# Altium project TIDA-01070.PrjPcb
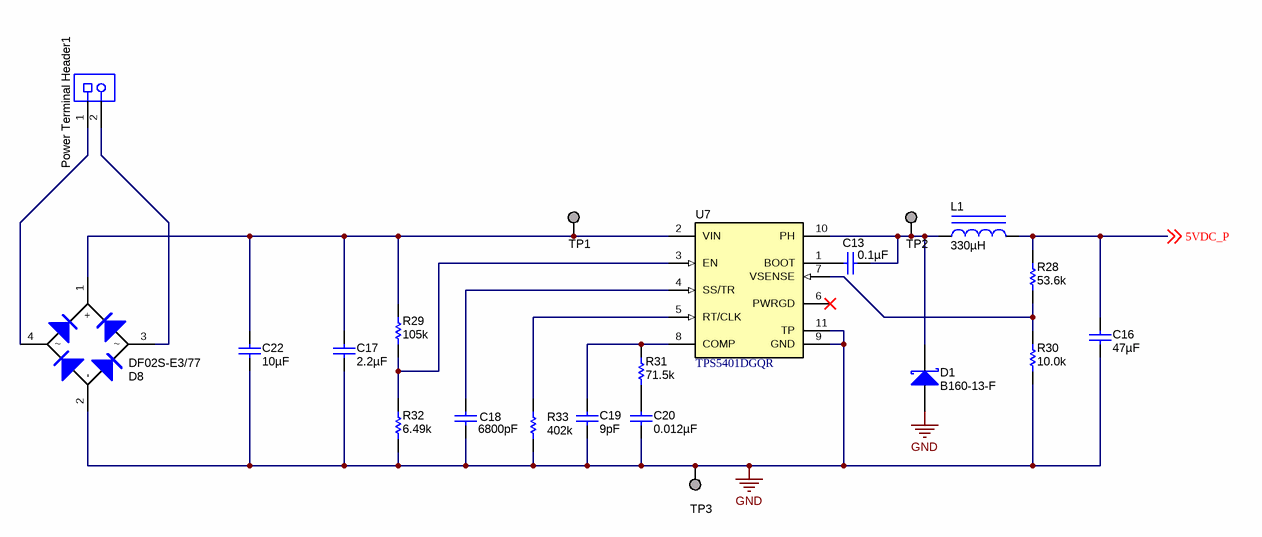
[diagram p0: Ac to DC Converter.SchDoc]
CopyrightYear: 2016; PCB_Layout: Krypton Solutions/RS; PCB_Rev: E1; PRJ_Customer: Public Release; PRJ_Engineer: Brian Dempsey; PRJ_Number: TIDA-01070; PRJ_Title: TIDA-01070; SCH_Rev: E1; TechSupport: http://www.ti.com/support; TID: TIDA-01070
5 sheets, 156 parts. Net scope: global (net labels, ports and power ports of the same name join across sheets).
Board file: TIDA-01070.PcbDoc
Sheets:
  Ac to DC Converter.SchDoc
  Board_IO_Interface.SchDoc
  Internal_Processing.SchDoc
  Sensor_Filtering.SchDoc
  TIDA-01070__EVM_Hardware.SchDoc

## Sheet Ac to DC Converter.SchDoc
size 431 x 279 mm; Date: Not shown in title block; ApprovedBy: Not shown in title block; CheckedBy: Not shown in title block; Author: Not shown in title block; CompanyName: Not shown in title block; Engineer: Not shown in title block; Organization: Not shown in title block; Address1: Not shown in title block; Address2: Not shown in title block; Address3: Not shown in title block; Address4: Not shown in title block; DocumentNumber: 1; Revision: Use project parameter SCH_Rev; SheetNumber: 1; SheetTotal: 5; PageSetup: Record=PageOptions¦CenterHorizontal=True¦CenterVertical=True¦PrintScale=1.00¦XCorrection=1.00¦YCorrection=1.00¦PrintKind=0¦BorderSize=5000000¦LeftOffset=0¦BottomOffset=0¦Orientation=2¦PaperLength=1000¦PaperWidth=1000¦Scale=100¦PaperSource=15¦PrintQuality=600¦MediaType=1¦DitherType=10¦PaperKind=Letter¦PrintScaleMode=1

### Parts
C13  ValueDisplayed: 0.1µF  [0402]  (hidden comment: GRM155R61A104KA01D)
C16  ValueDisplayed: 47µF  [1206_180]  (hidden comment: GRM31CR61A476KE15L)
C17  ValueDisplayed: 2.2µF  [1210_270]  (hidden comment: GRM32ER72A225KA35L)
C18  ValueDisplayed: 6800pF  [0805_HV]  (hidden comment: CC0805KRX7R9BB682)
C19  ValueDisplayed: 9pF  [0805_HV]  (hidden comment: GQM2195C2A9R0CB01D)
C20  ValueDisplayed: 0.012µF  [0201]  (hidden comment: GRM033C80J123KE01D)
C22  ValueDisplayed: 10µF  [2220_280]  (hidden comment: 22201C106MAT2A)
D1  B160-13-F  [SMA]
D8  DF02S-E3/77  [DF-S]
L1  ValueDisplayed: 330µH  [SDR0604]  (hidden comment: SDR0604-331KL)
Power_Terminal_Header1  (no value)  [On-Shore_OSTTE020161]
R28  ValueDisplayed: 53.6k  [0402]  (hidden comment: CRCW040253K6FKED)
R29  ValueDisplayed: 105k  [0402]  (hidden comment: CRCW0402105KFKED)
R30  ValueDisplayed: 10.0k  [0402]  (hidden comment: CRCW040210K0FKED)
R31  ValueDisplayed: 71.5k  [0402]  (hidden comment: CRCW040271K5FKED)
R32  ValueDisplayed: 6.49k  [0402]  (hidden comment: CRCW04026K49FKED)
R33  ValueDisplayed: 402k  [0402]  (hidden comment: CRCW0402402KFKED)
TP1  TESTPOINT  [Keystone_5019]  (value not drawn)  (no BOM)
TP2  TESTPOINT  [Keystone_5019]  (value not drawn)  (no BOM)
TP3  TESTPOINT  [Keystone_5019]  (value not drawn)  (no BOM)
U7  TPS5401DGQR  [DGQ0010D_N]

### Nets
GND: C16.2 C17.2 C18.2 C19.2 C20.2 C22.2 D1.2(A) D8.2(-) R30.1 R32.1 R33.1 TP3.1 U7.9(GND) U7.11(TP)
5VDC_P: C16.1 L1.2 R28.2 ; off-sheet 5VDC_P
NetC13_1: C13.1 U7.1(BOOT)
NetC13_2: C13.2 D1.1(K) L1.1 TP2.1 U7.10(PH)
NetC17_1: C17.1 C22.1 D8.1(+) R29.2 TP1.1 U7.2(VIN)
NetC18_1: C18.1 U7.4(SS/TR)
NetC19_1: C19.1 R31.2 U7.8(COMP)
NetC20_1: C20.1 R31.1
NetD8_3: D8.3 Power_Terminal_Header1.2
NetD8_4: D8.4 Power_Terminal_Header1.1
NetR28_1: R28.1 R30.2 U7.7(VSENSE)
NetR29_1: R29.1 R32.2 U7.3(EN)
NetR33_2: R33.2 U7.5(RT/CLK)

Not connected (* = marked no-connect by the designer): U7 6(PWRGD)*

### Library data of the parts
C13 = GRM155R61A104KA01D: CAP, CERM, 0.1 µF, 10 V, +/- 10%, X5R, 0402; Manufacturer: MuRata; Polarized: N; CompType: Capacitor; Value: 0.1uF; U/M: EA; Cap_F: 0.0000001; Tolerance_%: 10; Value1: Unknown; Value2: 10V; TaMin_C: -55; TaMax_C: 85; SizeArea_mm2: 0.5; SizeAreaWB_mm2: 3; SizeX_mm: 1; SizeZ_mm: 0.6; AEC Category: Q200
C16 = GRM31CR61A476KE15L: CAP, CERM, 47 µF, 10 V, +/- 10%, X5R, 1206; Manufacturer: MuRata; Polarized: N; CompType: Capacitor; Value: 47uF; U/M: EA; Cap_F: 0.000047; Tolerance_%: 10; Value1: Unknown; Value2: 10V; TaMin_C: -55; TaMax_C: 85; Cap_Case: 1206; SizeArea_mm2: 5.12; SizeAreaWB_mm2: 10.92; SizeX_mm: 3.2; SizeY_mm: 1.6; SizeZ_mm: 1.8; AEC Category: Q200
C17 = GRM32ER72A225KA35L: CAP, CERM, 2.2 µF, 100 V, +/- 10%, X7R, 1210; Manufacturer: MuRata; Polarized: N; CompType: Capacitor; Value: 2.2uF; U/M: EA; Cap_F: 0.0000022; Tolerance_%: 10; ESR_ohm: 0.007; Value1: 0.007 ohm; VDC_V: 100; Value2: 100V; IRMS_A: 4.4; TaMin_C: -55; TaMax_C: 125; Cap_Case: 1210; SizeArea_mm2: 8; SizeAreaWB_mm2: 14.7; SizeX_mm: 3.2; SizeY_mm: 2.5; SizeZ_mm: 2.7; AEC Category: Q200
C18 = CC0805KRX7R9BB682: CAP, CERM, 6800 pF, 50 V, +/- 10%, X7R, 0805; Manufacturer: Yageo America; Polarized: N; CompType: Capacitor; Value: 6800pF; U/M: EA; Cap_F: 0.0000000068; Tolerance_%: 10; Value1: Unknown; VDC_V: 50; Value2: 50V; TaMin_C: -55; TaMax_C: 125; Cap_Case: 0805; SizeArea_mm2: 2.5; SizeAreaWB_mm2: 6.75; SizeX_mm: 2; SizeY_mm: 1.25; SizeZ_mm: 1.45; AEC Category: Q200
C19 = GQM2195C2A9R0CB01D: CAP, CERM, 9 pF, 100 V, +/- 5%, C0G/NP0, 0805; Manufacturer: MuRata; Polarized: N; CompType: Capacitor; Value: 9pF; U/M: EA; Cap_F: 0.000000000009; Tolerance_%: 5; Value1: Unknown; VDC_V: 100; Value2: 100V; TaMin_C: -55; TaMax_C: 125; Cap_Case: 0805; SizeArea_mm2: 2.5; SizeAreaWB_mm2: 6.75; SizeX_mm: 2; SizeY_mm: 1.25; SizeZ_mm: 1.45; AEC Category: Q200
C20 = GRM033C80J123KE01D: CAP, CERM, 0.012 µF, 6.3 V, +/- 10%, X6S, 0201; Manufacturer: MuRata; Polarized: N; CompType: Capacitor; Value: 0.012uF; U/M: EA; Cap_F: 0.000000012; Tolerance_%: 10; Value1: Unknown; VDC_V: 6.3; Value2: 6.3V; TaMin_C: -55; TaMax_C: 105; SizeArea_mm2: 0.18; SizeAreaWB_mm2: 2.08; SizeX_mm: 0.6; SizeY_mm: 0.3; SizeZ_mm: 0.26; AEC Category: Q200
C22 = 22201C106MAT2A: CAP, CERM, 10 µF, 100 V, +/- 20%, X7R, 2220; Manufacturer: AVX; Polarized: N; CompType: Capacitor; Value: 10uF; U/M: EA; Cap_F: 0.00001; Tolerance_%: 20; Value1: Unknown; VDC_V: 100; Value2: 100V; TaMin_C: -55; TaMax_C: 125; Cap_Case: 2220; SizeAreaWB_mm2: 53.9; SizeArea_mm2: 28.5; SizeX_mm: 5.7; SizeY_mm: 5; SizeZ_mm: 2.8; AEC Category: Q200
D1 = B160-13-F: Diode, Schottky, 60 V, 1 A, SMA; Manufacturer: Diodes Inc.; U/M: EA; Vf_V: 0.7; Value: 60V; Value1: 1A; Value2: 0.7V; Io_A: 1; Vr_V: 60; TJmax_C: 150; RJC_CperW: 20; SizeAreaWB_mm2: 37.3428; SizeArea_mm2: 16.3228; SizeX_mm: 5.59; SizeY_mm: 2.92; SizeZ_mm: 2.87; AEC Category: Q101
D8 = DF02S-E3/77: Diode, Switching-Bridge, 200 V, 1 A, DF-S; Manufacturer: Vishay-Semiconductor; U/M: EA; Vf_V: 1.1; Value: 200V; Value1: 1A; Value2: 1.1V; Io_A: 1; Vr_V: 200; TJmax_C: 150; RJC_CperW: 15; SizeAreaWB_mm2: 98.794; SizeArea_mm2: 62.974; SizeX_mm: 7.4; SizeY_mm: 8.51; SizeZ_mm: 3.4; AEC Category: Q101
L1 = SDR0604-331KL: Inductor, Drum Core, Ferrite, 330 µH, 0.27 A, 2.25 ohm, SMD; Manufacturer: Bourns; Value: 330uH; Ind_H: 330.0E-6; Imax_A: 0.27; Irms: 0.27A @ 40C rise; Isat: 0.42A @ 10% inductance drop; DCR_ohm: 2.25; Value2: 0.27A; AEC Category: Q200
Power_Terminal_Header1 = OSTTE020161: Terminal Block, 2x1, 3.5mm, TH; Manufacturer: On-Shore Technology; SymbolCreator: a0412235
R28 = CRCW040253K6FKED: RES, 53.6 k, 1%, 0.063 W, 0402; Manufacturer: Vishay-Dale; CompType: Resistor; Value: 53.6k; Res_ohm: 53600; Value_Code: 53k6; Tolerance_%: 1; Power_W: 0.063; Value2: 0.063W; VDC_V: 50; TempCo: 100 ppm/C; SizeArea_mm2: 0.5; SizeZ_mm: 0.6; EIA_Code: E96; U/M: EA; AEC Category: Q200
R29 = CRCW0402105KFKED: RES, 105 k, 1%, 0.063 W, 0402; Manufacturer: Vishay-Dale; CompType: Resistor; Value: 105k; Res_ohm: 105000; Tolerance_%: 1; Power_W: 0.063; Value2: 0.063W; VDC_V: 50; TempCo: 100 ppm/C; SizeArea_mm2: 0.5; SizeZ_mm: 0.6; EIA_Code: E96; U/M: EA; AEC Category: Q200
R30 = CRCW040210K0FKED: RES, 10.0 k, 1%, 0.063 W, 0402; Manufacturer: Vishay-Dale; CompType: Resistor; Value: 10.0k; Res_ohm: 10000; Value_Code: 10k0; Tolerance_%: 1; Power_W: 0.063; Value2: 0.063W; VDC_V: 50; TempCo: 100 ppm/C; SizeArea_mm2: 0.5; SizeZ_mm: 0.6; EIA_Code: E96; U/M: EA; AEC Category: Q200
R31 = CRCW040271K5FKED: RES, 71.5 k, 1%, 0.063 W, 0402; Manufacturer: Vishay-Dale; CompType: Resistor; Value: 71.5k; Res_ohm: 71500; Value_Code: 71k5; Tolerance_%: 1; Power_W: 0.063; Value2: 0.063W; VDC_V: 50; TempCo: 100 ppm/C; SizeArea_mm2: 0.5; SizeZ_mm: 0.6; EIA_Code: E96; U/M: EA; AEC Category: Q200
R32 = CRCW04026K49FKED: RES, 6.49 k, 1%, 0.063 W, 0402; Manufacturer: Vishay-Dale; CompType: Resistor; Value: 6.49k; Res_ohm: 6490; Value_Code: 6k49; Tolerance_%: 1; Power_W: 0.063; Value2: 0.063W; VDC_V: 50; TempCo: 100 ppm/C; SizeArea_mm2: 0.5; SizeZ_mm: 0.6; EIA_Code: E96; U/M: EA; AEC Category: Q200
R33 = CRCW0402402KFKED: RES, 402 k, 1%, 0.063 W, 0402; Manufacturer: Vishay-Dale; CompType: Resistor; Value: 402k; Res_ohm: 402000; Tolerance_%: 1; Power_W: 0.063; Value2: 0.063W; VDC_V: 50; TempCo: 100 ppm/C; SizeArea_mm2: 0.5; SizeZ_mm: 0.6; EIA_Code: E96; U/M: EA; AEC Category: Q200
TP1-TP3 = 5019: Test Point, Miniature, SMT; Manufacturer: Keystone; CompType: Test Point Loop
U7 = TPS5401DGQR: Buck Step Down Regulator with 3.5 to 42 V Input and 0.8 to 39 V Output, -40 to 150 degC, 10-Pin MSOP-PowerPAD (DGQ), Green (RoHS & no Sb/Br); Manufacturer: Texas Instruments; Alternate PartNumber: Equivalent; Duty Cycle(Max)(%): 98; Iout(Max)(A): 0.5; Iq(Typ)(mA): 0.116; Rating: Catalog; Regulated Outputs(#): 1; SubFamily: Step-Down Regulator; Switch Current Limit(Typ)(A): 0.94; Vin(Max)(V): 42; Vin(Min)(V): 3.5; Vout(Max)(V): 39; Vout(Min)(V): 0.8

## Sheet Board_IO_Interface.SchDoc
size 431 x 279 mm; Date: Not shown in title block; ApprovedBy: Not shown in title block; CheckedBy: Not shown in title block; Author: Not shown in title block; CompanyName: Not shown in title block; Engineer: Brian Dempsey; Organization: Not shown in title block; Address1: Not shown in title block; Address2: Not shown in title block; Address3: Not shown in title block; Address4: Not shown in title block; DocumentNumber: 1; Revision: Use project parameter SCH_Rev; SheetNumber: 2; SheetTotal: 5; PageSetup: Record=PageOptions¦CenterHorizontal=True¦CenterVertical=True¦PrintScale=1.00¦XCorrection=1.00¦YCorrection=1.00¦PrintKind=0¦BorderSize=5000000¦LeftOffset=0¦BottomOffset=0¦Orientation=2¦PaperLength=1000¦PaperWidth=1000¦Scale=100¦PaperSource=15¦PrintQuality=600¦MediaType=1¦DitherType=10¦PaperKind=Letter¦PrintScaleMode=1
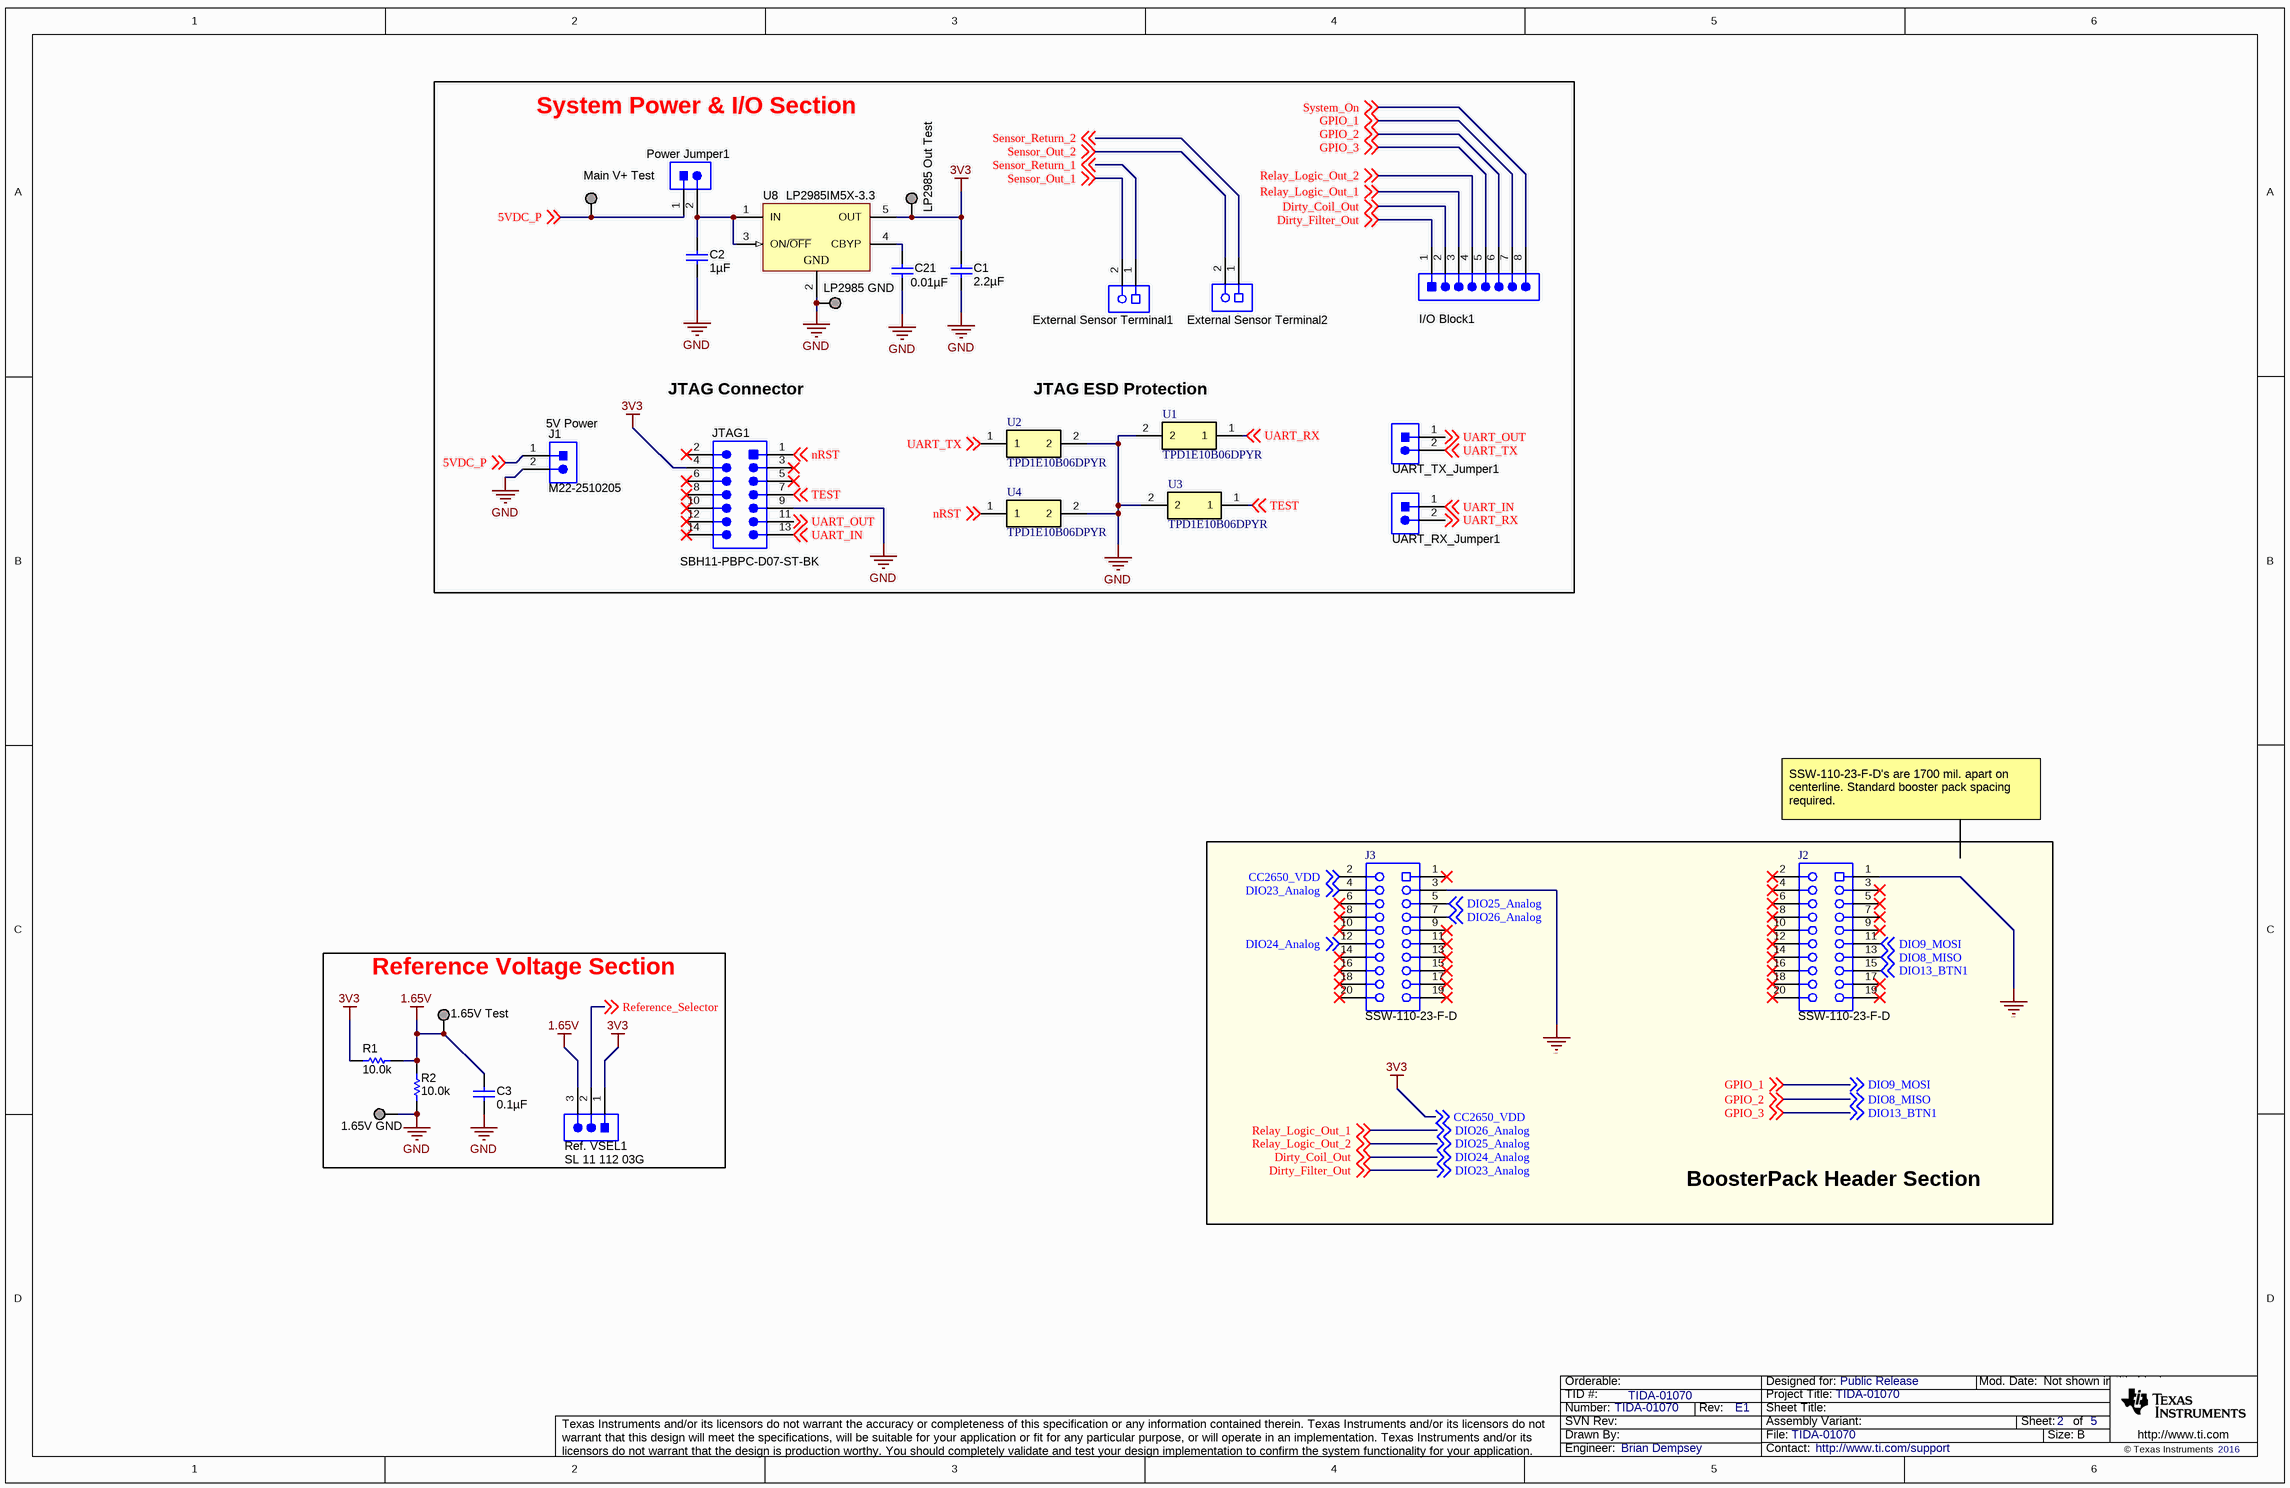
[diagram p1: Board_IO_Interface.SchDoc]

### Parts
1.65V_GND  TESTPOINT  [Keystone_5019]  (value not drawn)  (no BOM)
1.65V_Test  TESTPOINT  [Keystone_5019]  (value not drawn)  (no BOM)
C1  ValueDisplayed: 2.2µF  [0402]  (hidden comment: GRM155C80J225KE95D)
C2  ValueDisplayed: 1µF  [0402]  (hidden comment: GRM155R60J105KE19D)
C3  ValueDisplayed: 0.1µF  [0603]  (hidden comment: 0603YC104JAT2A)
C21  ValueDisplayed: 0.01µF  [0201]  (hidden comment: GRM033R60J103KA01D)
External_Sensor_Terminal1  OSTTE020161  [On-Shore_OSTTE020161]  (value not drawn)
External_Sensor_Terminal2  OSTTE020161  [On-Shore_OSTTE020161]  (value not drawn)
I/O_Block1  ED555/8DS  [On-Shore_ED555_8DS]  (value not drawn)
J1  M22-2510205  [Harwin_M22-2510205]
J2  SSW-110-23-F-D  [CONN_SSW-110-23-F-D]
J3  SSW-110-23-F-D  [CONN_SSW-110-23-F-D]
JTAG1  SBH11-PBPC-D07-ST-BK  [CONN_SBH11-PBPC-D07-ST-BK]
LP2985_GND  TESTPOINT  [Keystone_5019]  (value not drawn)  (no BOM)
LP2985_Out_Test  TESTPOINT  [Keystone_5019]  (value not drawn)  (no BOM)
Main_V+_Test  TESTPOINT  [Keystone_5019]  (value not drawn)  (no BOM)
Power_Jumper1  PartNumber  [TE_5-146278-2]  (value not drawn)
R1  ValueDisplayed: 10.0k  [0402]  (hidden comment: CRCW040210K0FKED)
R2  ValueDisplayed: 10.0k  [0402]  (hidden comment: CRCW040210K0FKED)
Ref._VSEL1  SL 11 112 03G  [Fischer_SL-11-112-03G]
U1  TPD1E10B06DPYR  [DPY0002A]
U2  TPD1E10B06DPYR  [DPY0002A]
U3  TPD1E10B06DPYR  [DPY0002A]
U4  TPD1E10B06DPYR  [DPY0002A]
U8  LP2985IM5X-3.3  [MF05A_N]
UART_RX_Jumper1  M22-2510205  [Harwin_M22-2510205]  (value not drawn)
UART_TX_Jumper1  M22-2510205  [Harwin_M22-2510205]  (value not drawn)

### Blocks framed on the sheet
System Power & I/O Section: C1 C2 C21 External_Sensor_Terminal1 External_Sensor_Terminal2 I/O_Block1 J1 JTAG1 LP2985_GND LP2985_Out_Test Main_V+_Test Power_Jumper1 U1-U4 U8 UART_RX_Jumper1 UART_TX_Jumper1
BoosterPack Header Section: J2 J3
Reference Voltage Section: 1.65V_GND 1.65V_Test C3 R1 R2 Ref._VSEL1

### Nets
1.65V: 1.65V_Test.1 C3.2 R1.1 R2.1 Ref._VSEL1.3
3V3: C1.1 J3.2 JTAG1.4 LP2985_Out_Test.1 R1.2 Ref._VSEL1.1 U8.5(OUT) ; off-sheet CC2650_VDD  [also labelled CC2650_VDD]
GND: 1.65V_GND.1 C1.2 C2.2 C3.1 C21.2 J1.2 J2.1 J3.3 JTAG1.9 LP2985_GND.1 R2.2 U1.2 U2.2 U3.2 U4.2 U8.2(GND)
5VDC_P: J1.1 Main_V+_Test.1 Power_Jumper1.1 ; off-sheet 5VDC_P
DIO8_MISO: I/O_Block1.6 J2.13 ; off-sheet DIO8_MISO, off-sheet GPIO_2  [also labelled GPIO_2]
DIO9_MOSI: I/O_Block1.7 J2.11 ; off-sheet DIO9_MOSI, off-sheet GPIO_1  [also labelled GPIO_1]
DIO13_BTN1: I/O_Block1.5 J2.15 ; off-sheet DIO13_BTN1, off-sheet GPIO_3  [also labelled GPIO_3]
DIO23_Analog: I/O_Block1.1 J3.4 ; off-sheet DIO23_Analog, off-sheet Dirty_Filter_Out  [also labelled Dirty_Filter_Out]
DIO24_Analog: I/O_Block1.2 J3.12 ; off-sheet DIO24_Analog, off-sheet Dirty_Coil_Out  [also labelled Dirty_Coil_Out]
DIO25_Analog: I/O_Block1.4 J3.5 ; off-sheet Relay_Logic_Out_2, off-sheet DIO25_Analog  [also labelled Relay_Logic_Out_2]
DIO26_Analog: I/O_Block1.3 J3.7 ; off-sheet Relay_Logic_Out_1, off-sheet DIO26_Analog  [also labelled Relay_Logic_Out_1]
nRST: JTAG1.1 U4.1 ; off-sheet nRST
Reference_Selector: Ref._VSEL1.2 ; off-sheet Reference_Selector
Sensor_Out_1: External_Sensor_Terminal1.2 ; off-sheet Sensor_Out_1
Sensor_Out_2: External_Sensor_Terminal2.2 ; off-sheet Sensor_Out_2
Sensor_Return_1: External_Sensor_Terminal1.1 ; off-sheet Sensor_Return_1
Sensor_Return_2: External_Sensor_Terminal2.1 ; off-sheet Sensor_Return_2
System_On: I/O_Block1.8 ; off-sheet System_On
TEST: JTAG1.7 U3.1 ; off-sheet TEST
UART_IN: JTAG1.13 UART_RX_Jumper1.1 ; off-sheet UART_IN
UART_OUT: JTAG1.11 UART_TX_Jumper1.1 ; off-sheet UART_OUT
UART_RX: U1.1 UART_RX_Jumper1.2 ; off-sheet UART_RX
UART_TX: U2.1 UART_TX_Jumper1.2 ; off-sheet UART_TX
NetC2_1: C2.1 Power_Jumper1.2 U8.1(IN) U8.3(ON/~{OFF})
NetC21_1: C21.1 U8.4(CBYP)

Not connected (* = marked no-connect by the designer): J2 2* 3* 4* 5* 6* 7* 8* 9* 10* 12* 14* 16* 17* 18* 19* 20*; J3 1* 6* 8* 9* 10* 11* 13* 14* 15* 16* 17* 18* 19* 20*; JTAG1 2* 3* 5* 6* 8* 10* 12* 14*

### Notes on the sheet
- (near J1) 5V Power
- JTAG Connector
- JTAG ESD Protection
- SSW-110-23-F-D's are 1700 mil. apart on centerline. Standard booster pack spacing required.

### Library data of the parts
1.65V_GND 1.65V_Test LP2985_GND LP2985_Out_Test Main_V+_Test = 5019: as TP1 on sheet Ac to DC Converter
C1 = GRM155C80J225KE95D: CAP, CERM, 2.2 µF, 6.3 V, +/- 10%, X6S, 0402; Manufacturer: MuRata; Polarized: N; CompType: Capacitor; Value: 2.2uF; U/M: EA; Cap_F: 0.0000022; Tolerance_%: 10; Value1: Unknown; VDC_V: 6.3; Value2: 6.3V; TaMin_C: -55; TaMax_C: 105; AEC Category: Q200; SizeArea_mm2: 0.5; SizeAreaWB_mm2: 3; SizeX_mm: 1; SizeZ_mm: 0.6
C2 = GRM155R60J105KE19D: CAP, CERM, 1 µF, 6.3 V, +/- 10%, X5R, 0402; Manufacturer: MuRata; Polarized: N; CompType: Capacitor; Value: 1uF; U/M: EA; Cap_F: 0.000001; Tolerance_%: 10; Value1: Unknown; VDC_V: 6.3; Value2: 6.3V; TaMin_C: -55; TaMax_C: 85; AEC Category: Q200; SizeArea_mm2: 0.5; SizeAreaWB_mm2: 3; SizeX_mm: 1; SizeZ_mm: 0.6
C3 = 0603YC104JAT2A: CAP, CERM, 0.1 µF, 16 V, +/- 5%, X7R, 0603; Manufacturer: AVX; Polarized: N; CompType: Capacitor; Value: 0.1uF; U/M: EA; Cap_F: 0.0000001; Tolerance_%: 5; ESR_ohm: 0.039; Value1: 0.039 ohm; VDC_V: 16; Value2: 16V; TaMin_C: -55; TaMax_C: 125; SizeArea_mm2: 1.28; SizeAreaWB_mm2: 4.68; SizeX_mm: 1.6; SizeY_mm: 0.8; SizeZ_mm: 1; AEC Category: Q200
C21 = GRM033R60J103KA01D: CAP, CERM, 0.01 µF, 6.3 V, +/- 10%, X5R, 0201; Manufacturer: MuRata; Polarized: N; CompType: Capacitor; Value: 0.01uF; U/M: EA; Cap_F: 0.00000001; Tolerance_%: 10; Value1: Unknown; VDC_V: 6.3; Value2: 6.3V; TaMin_C: -55; TaMax_C: 85; SizeArea_mm2: 0.18; SizeAreaWB_mm2: 2.08; SizeX_mm: 0.6; SizeY_mm: 0.3; SizeZ_mm: 0.26; AEC Category: Q200
External_Sensor_Terminal1 External_Sensor_Terminal2 = OSTTE020161: as Power_Terminal_Header1 on sheet Ac to DC Converter
I/O_Block1 = ED555/8DS: Terminal Block, 3.5mm, 8-Pos, TH; Manufacturer: On-Shore Technology; SymbolCreator: a0411947; Pitch_mm: 3.5; Gender: Male; Shrouded: Y; Row_Count: 1; ContactFinish: Brass
J1 UART_RX_Jumper1 UART_TX_Jumper1 = M22-2510205: Header, 2mm, 2x1, Gold, Black, TH; Manufacturer: Harwin; SymbolCreator: a0412235; Pitch_mm: 2; Gender: Male; Shrouded: N; Row_Count: 1; Voltage_V: 500; Cert_UL: Y
J2 J3 = SSW-110-23-F-D: Connector, Receptacle, 100mil, 10x2, Gold plated, TH; Manufacturer: Samtec; SymbolCreator: a0412235
JTAG1 = SBH11-PBPC-D07-ST-BK: Header (shrouded), 100 mil, 7x2, Gold, TH; Manufacturer: Sullins Connector Solutions; SymbolCreator: a0412235
Power_Jumper1 = 5-146278-2: Header, 100mil, 2x1, Tin, TH; Manufacturer: TE Connectivity; SymbolCreator: a0412235
R1 R2 = CRCW040210K0FKED: as R30 on sheet Ac to DC Converter
Ref._VSEL1 = SL 11 112 03G: Header, 2.54mm, 3x1, Gold, TH; Manufacturer: Fischer Elektronik; SymbolCreator: a0799628
U1-U4 = TPD1E10B06DPYR: ESD in 0402 Package with 10 pF Capacitance and 6 V Breakdown, 1 Channel, -40 to +125 degC, 2-pin X2SON (DPY), Green (RoHS & no Sb/Br); Manufacturer: Texas Instruments; Alternate PartNumber: Equivalent; Breakdown Voltage(Min)(V): 6; Eco-Plan: TBD; IEC 61000-4-2 Air-Gap(+/- kV): 30; IO Capacitance(Typ)(pF): 10; SubFamily: ESD Solution
U8 = LP2985IM5X-3.3: Micropower 150 mA Low-Noise Ultra Low-Dropout Regulator, 5-pin SOT-23; PartNumber: LP2985IM5X-3.3/NOPB; Manufacturer: Texas Instruments; PackageTopMarking: L0RB*XTT; PowerWise: N; CompType: LDO IC

## Sheet Internal_Processing.SchDoc
size 431 x 279 mm; Date: Not shown in title block; ApprovedBy: Not shown in title block; CheckedBy: Not shown in title block; Author: Not shown in title block; CompanyName: Not shown in title block; Engineer: Not shown in title block; Organization: Not shown in title block; Address1: Not shown in title block; Address2: Not shown in title block; Address3: Not shown in title block; Address4: Not shown in title block; DocumentNumber: 1; Revision: Use project parameter SCH_Rev; SheetNumber: 3; SheetTotal: 5; PageSetup: Record=PageOptions¦CenterHorizontal=True¦CenterVertical=True¦PrintScale=1.00¦XCorrection=1.00¦YCorrection=1.00¦PrintKind=0¦BorderSize=5000000¦LeftOffset=0¦BottomOffset=0¦Orientation=2¦PaperLength=1000¦PaperWidth=1000¦Scale=100¦PaperSource=15¦PrintQuality=600¦MediaType=1¦DitherType=10¦PaperKind=Letter¦PrintScaleMode=1
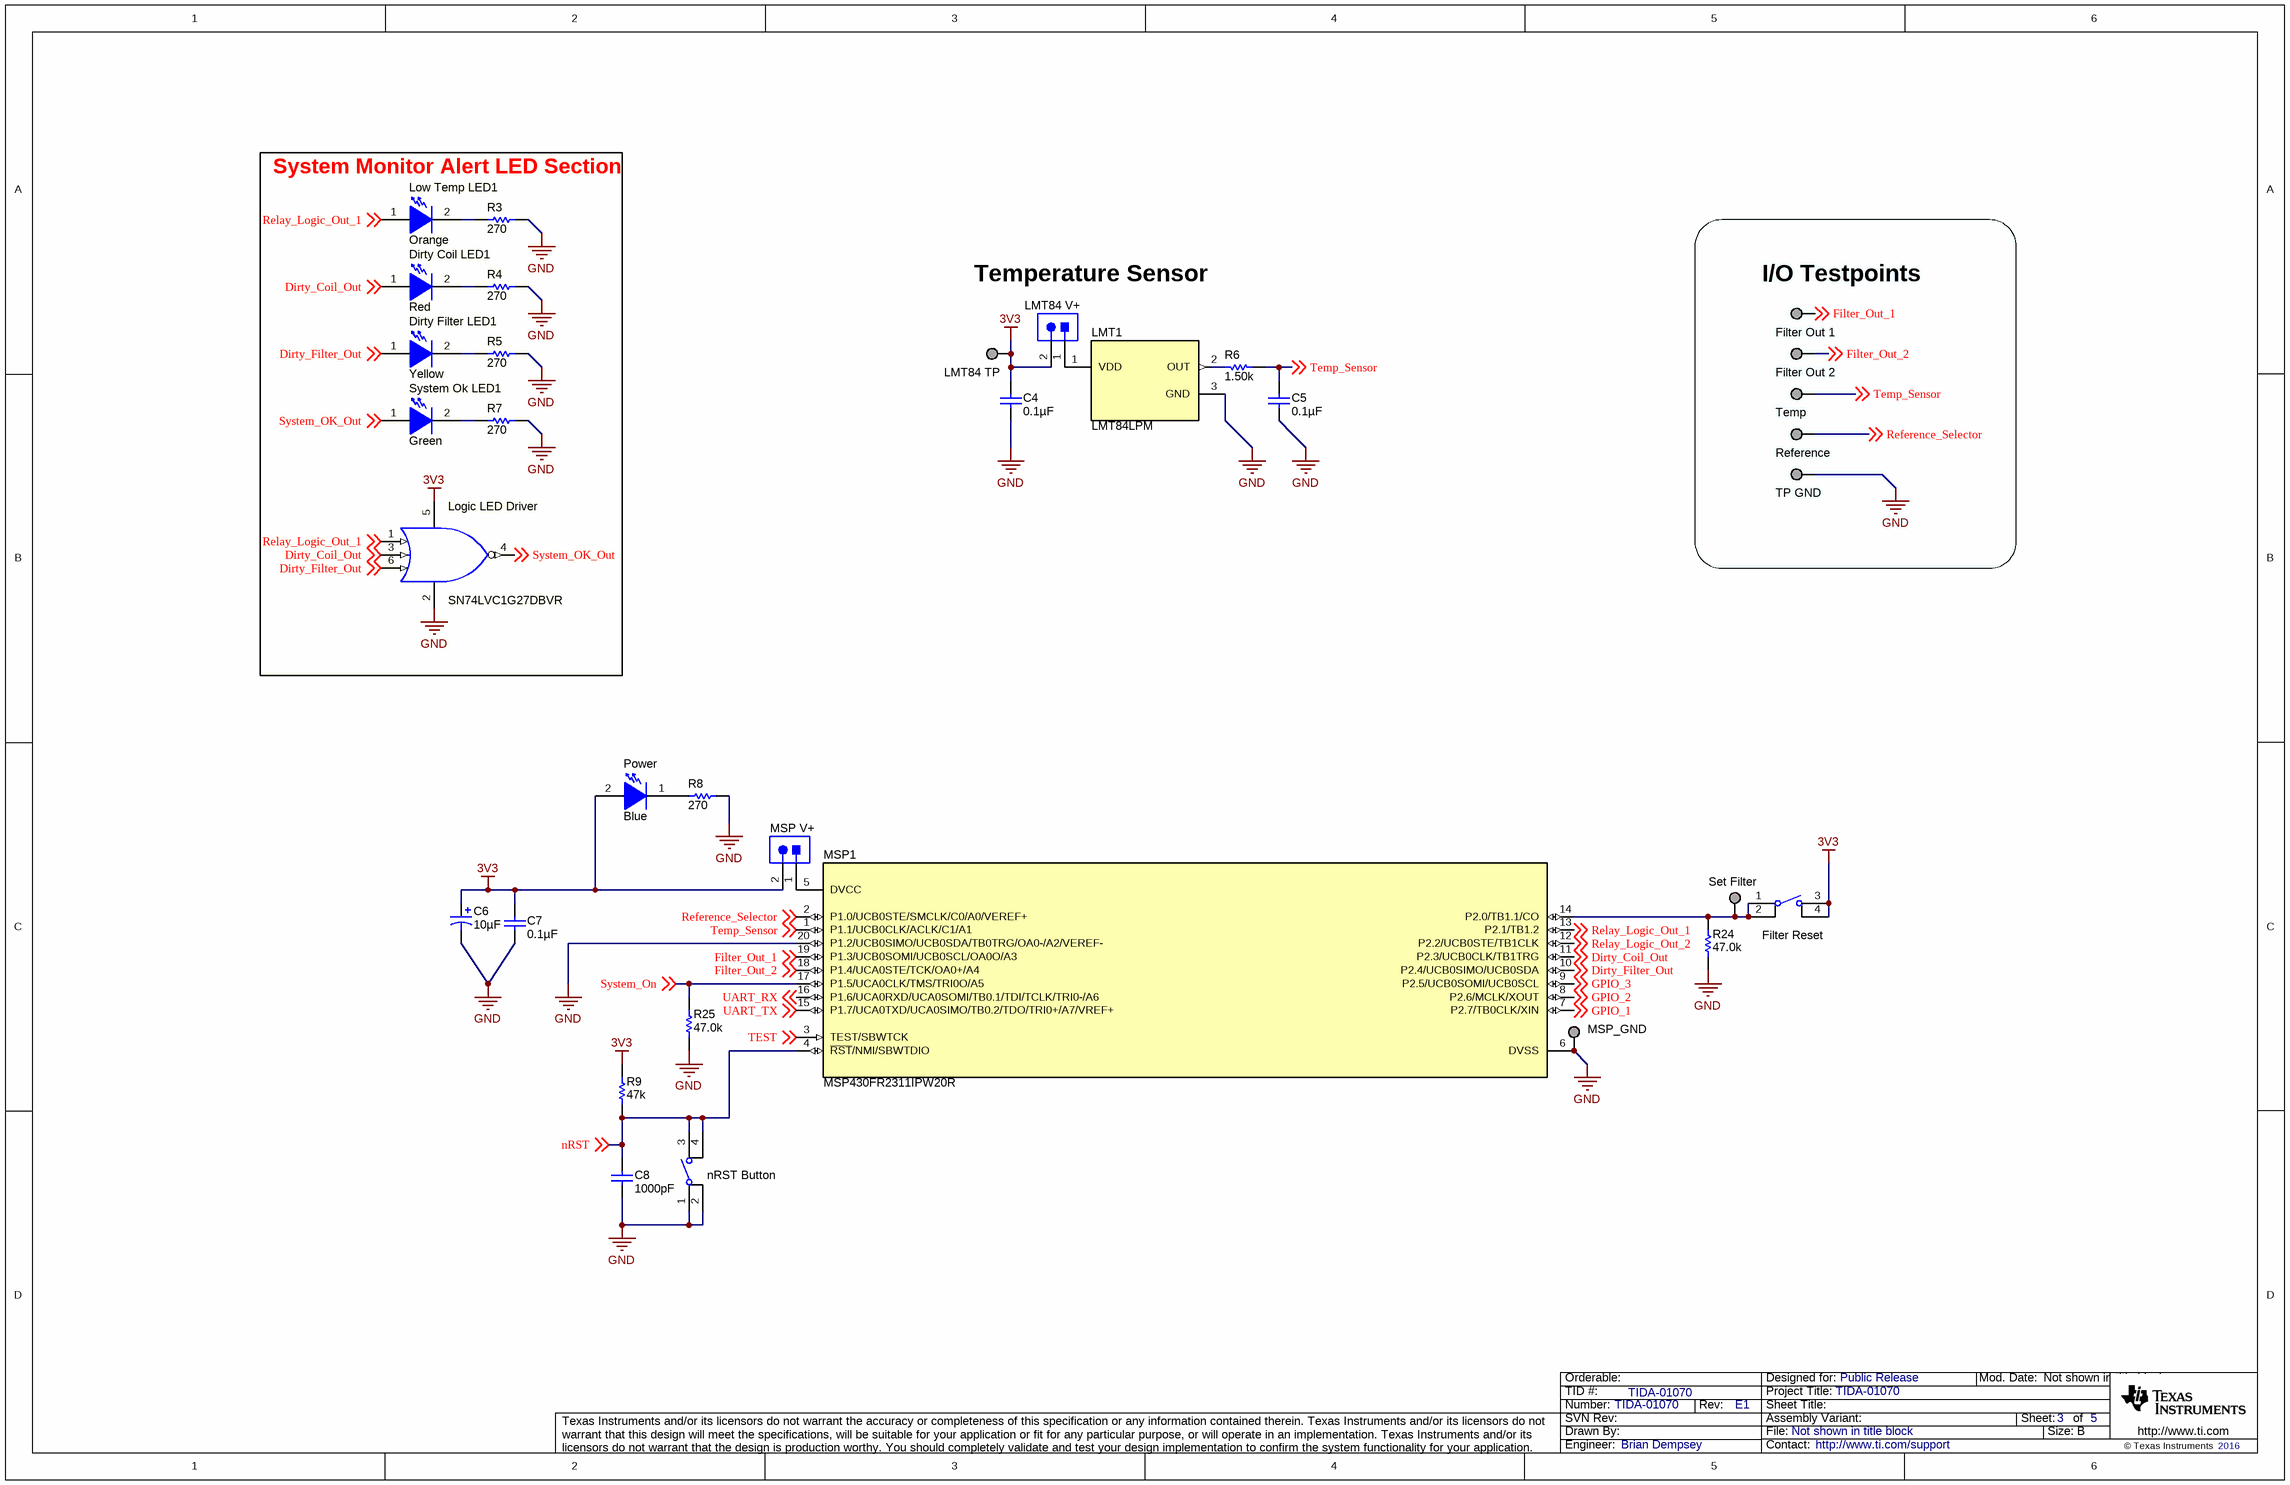
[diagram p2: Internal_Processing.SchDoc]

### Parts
C4  ValueDisplayed: 0.1µF  [0603]  (hidden comment: 0603YC104JAT2A)
C5  ValueDisplayed: 0.1µF  [0603]  (hidden comment: 0603YC104JAT2A)
C6  ValueDisplayed: 10µF  [SM_RADIAL_B]  (hidden comment: EEE-FK1E100R)
C7  ValueDisplayed: 0.1µF  [0603]  (hidden comment: 0603YC104JAT2A)
C8  ValueDisplayed: 1000pF  [0402]  (hidden comment: GRM155R71C102KA01D)
Dirty_Coil_LED1  value Red  [LED_LTST-C170_Red]  (hidden comment: LTST-C170KRKT)
Dirty_Filter_LED1  value Yellow  [LED_LTST-C170]  (hidden comment: LTST-C170KSKT)
Filter_Out_1  TESTPOINT  [Keystone_5019]  (value not drawn)  (no BOM)
Filter_Out_2  TESTPOINT  [Keystone_5019]  (value not drawn)  (no BOM)
Filter_Reset  4-1437565-1  [SW_FSM4JSMA]  (value not drawn)
LMT1  LMT84LPM  [LP0003A_straight]
LMT84_TP  TESTPOINT  [Keystone_5019]  (value not drawn)  (no BOM)
LMT84_V+  M22-2510205  [Harwin_M22-2510205]  (value not drawn)
Logic_LED_Driver  SN74LVC1G27DBVR  [DBV0006A_N]
Low_Temp_LED1  value Orange  [LTST-C170KFKT_Orange]  (hidden comment: LTST-C170KFKT)
MSP1  MSP430FR2311IPW20R  [PW0020A_N]
MSP_GND  TESTPOINT  [Keystone_5019]  (value not drawn)  (no BOM)
MSP_V+  M22-2510205  [Harwin_M22-2510205]  (value not drawn)
nRST_Button  4-1437565-1  [SW_FSM4JSMA]  (value not drawn)
Power  value Blue  [WL-SMCW_Blue]  (hidden comment: 150060BS75000)
R3  ValueDisplayed: 270  [0402]  (hidden comment: CRCW0402270RJNED)
R4  ValueDisplayed: 270  [0402]  (hidden comment: CRCW0402270RJNED)
R5  ValueDisplayed: 270  [0402]  (hidden comment: CRCW0402270RJNED)
R6  ValueDisplayed: 1.50k  [0402]  (hidden comment: CRCW04021K50FKED)
R7  ValueDisplayed: 270  [0402]  (hidden comment: CRCW0402270RJNED)
R8  ValueDisplayed: 270  [0402]  (hidden comment: CRCW0402270RJNED)
R9  ValueDisplayed: 47k  [0402]  (hidden comment: CRCW040247K0JNED)
R24  ValueDisplayed: 47.0k  [0805_HV]  (hidden comment: RG2012P-473-B-T5)
R25  ValueDisplayed: 47.0k  [0805_HV]  (hidden comment: RG2012P-473-B-T5)
Reference  TESTPOINT  [Keystone_5019]  (value not drawn)  (no BOM)
Set_Filter  TESTPOINT  [Keystone_5019]  (value not drawn)  (no BOM)
System_Ok_LED1  value Green  [LTST-C170KGKT_Green]  (hidden comment: LTST-C170KGKT)
Temp  TESTPOINT  [Keystone_5019]  (value not drawn)  (no BOM)
TP_GND  TESTPOINT  [Keystone_5019]  (value not drawn)  (no BOM)

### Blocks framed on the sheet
System Monitor Alert LED Section: Dirty_Coil_LED1 Dirty_Filter_LED1 Logic_LED_Driver Low_Temp_LED1 R3-R5 R7 System_Ok_LED1
I/O Testpoints: Filter_Out_1 Filter_Out_2 Reference Temp TP_GND

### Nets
3V3: C4.2 C6.1(+) C7.2 Filter_Reset.3 Filter_Reset.4 LMT84_TP.1 LMT84_V+.2 Logic_LED_Driver.5(VCC) MSP_V+.2 Power.2(A) R9.2
GND: C4.1 C5.1 C6.2(-) C7.1 C8.1 LMT1.3(GND) Logic_LED_Driver.2(GND) MSP1.6(DVSS) MSP1.20(P1.2/UCB0SIMO/UCB0SDA/TB0TRG/OA0-/A2/VEREF-) MSP_GND.1 nRST_Button.1 nRST_Button.2 R3.2 R4.2 R5.2 R7.2 R8.2 R24.1 R25.1 TP_GND.1
Dirty_Coil_Out: Dirty_Coil_LED1.1(A) Logic_LED_Driver.3(B) MSP1.11(P2.3/UCB0CLK/TB1TRG) ; off-sheet Dirty_Coil_Out  [project net DIO24_Analog]
Dirty_Filter_Out: Dirty_Filter_LED1.1(A) Logic_LED_Driver.6(C) MSP1.10(P2.4/UCB0SIMO/UCB0SDA) ; off-sheet Dirty_Filter_Out  [project net DIO23_Analog]
Filter_Out_1: Filter_Out_1.1 MSP1.19(P1.3/UCB0SOMI/UCB0SCL/OA0O/A3) ; off-sheet Filter_Out_1
Filter_Out_2: Filter_Out_2.1 MSP1.18(P1.4/UCA0STE/TCK/OA0+/A4) ; off-sheet Filter_Out_2
GPIO_1: MSP1.7(P2.7/TB0CLK/XIN) ; off-sheet GPIO_1  [project net DIO9_MOSI]
GPIO_2: MSP1.8(P2.6/MCLK/XOUT) ; off-sheet GPIO_2  [project net DIO8_MISO]
GPIO_3: MSP1.9(P2.5/UCB0SOMI/UCB0SCL) ; off-sheet GPIO_3  [project net DIO13_BTN1]
nRST: C8.2 MSP1.4(~{RST}/NMI/SBWTDIO) nRST_Button.3 nRST_Button.4 R9.1 ; off-sheet nRST
Reference_Selector: MSP1.2(P1.0/UCB0STE/SMCLK/C0/A0/VEREF+) Reference.1 ; off-sheet Reference_Selector
Relay_Logic_Out_1: Logic_LED_Driver.1(A) Low_Temp_LED1.1(A) MSP1.13(P2.1/TB1.2) ; off-sheet Relay_Logic_Out_1  [project net DIO26_Analog]
Relay_Logic_Out_2: MSP1.12(P2.2/UCB0STE/TB1CLK) ; off-sheet Relay_Logic_Out_2  [project net DIO25_Analog]
System_OK_Out: Logic_LED_Driver.4(Y) System_Ok_LED1.1(A) ; off-sheet System_OK_Out
System_On: MSP1.17(P1.5/UCA0CLK/TMS/TRI0O/A5) R25.2 ; off-sheet System_On
Temp_Sensor: C5.2 MSP1.1(P1.1/UCB0CLK/ACLK/C1/A1) R6.2 Temp.1 ; off-sheet Temp_Sensor
TEST: MSP1.3(TEST/SBWTCK) ; off-sheet TEST
UART_RX: MSP1.16(P1.6/UCA0RXD/UCA0SOMI/TB0.1/TDI/TCLK/TRI0-/A6) ; off-sheet UART_RX
UART_TX: MSP1.15(P1.7/UCA0TXD/UCA0SIMO/TB0.2/TDO/TRI0+/A7/VREF+) ; off-sheet UART_TX
NetDirty_Coil_LED1_2: Dirty_Coil_LED1.2(K) R4.1
NetDirty_Filter_LED1_2: Dirty_Filter_LED1.2(K) R5.1
NetFilter_Reset_1: Filter_Reset.1 Filter_Reset.2 MSP1.14(P2.0/TB1.1/CO) R24.2 Set_Filter.1
NetLMT1_1: LMT1.1(VDD) LMT84_V+.1
NetLMT1_2: LMT1.2(OUT) R6.1
NetLow_Temp_LED1_2: Low_Temp_LED1.2(K) R3.1
NetMSP1_5: MSP1.5(DVCC) MSP_V+.1
NetPower_1: Power.1(K) R8.1
NetR7_1: R7.1 System_Ok_LED1.2(K)

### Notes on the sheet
- Temperature Sensor

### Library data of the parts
C4 C5 C7 = 0603YC104JAT2A: as C3 on sheet Board_IO_Interface
C6 = EEE-FK1E100R: CAP, AL, 10 µF, 25 V, +/- 20%, 1.35 ohm, AEC-Q200 Grade 2, SMD; Manufacturer: Panasonic; Polarized: Y; CompType: Capacitor; Value: 10uF; U/M: EA; Cap_F: 0.00001; Tolerance_%: 20; VDC_V: 25; Value2: 25V; ESR_ohm: 1.35; IRMS_A: 0.09; TaMin_C: -55; TaMax_C: 105; Cap_Case: B; AEC Category: Q200; AEC Grade: 2
C8 = GRM155R71C102KA01D: CAP, CERM, 1000 pF, 16 V, +/- 10%, X7R, 0402; Manufacturer: MuRata; Polarized: N; CompType: Capacitor; Value: 1000pF; U/M: EA; Cap_F: 0.000000001; Tolerance_%: 10; Value1: Unknown; VDC_V: 16; Value2: 16V; TaMin_C: -55; TaMax_C: 125; SizeArea_mm2: 0.5; SizeAreaWB_mm2: 3; SizeX_mm: 1; SizeZ_mm: 0.6; AEC Category: Q200
Dirty_Coil_LED1 = LTST-C170KRKT: LED, Red, SMD; Manufacturer: Lite-On; Vf_V: 2; Value2: 2V; Io_A: 0.02; Value1: W; SizeAreaWB_mm2: 6.75; SizeArea_mm2: 2.5; SizeY_mm: 1.25; SizeZ_mm: 1.2; U/M: EA
Dirty_Filter_LED1 = LTST-C170KSKT: LED, Yellow , SMD; Manufacturer: Lite-On; Vf_V: 2; Value2: 2V; Io_A: 0.02; Value1: W; SizeAreaWB_mm2: 6.75; SizeArea_mm2: 2.5; SizeY_mm: 1.25; SizeZ_mm: 1.2; U/M: EA
Filter_Out_1 Filter_Out_2 LMT84_TP MSP_GND Reference Set_Filter Temp TP_GND = 5019: as TP1 on sheet Ac to DC Converter
Filter_Reset nRST_Button = 4-1437565-1: Switch, Tactile, SPST-NO, 0.05A, 12V, SMT; Manufacturer: TE Connectivity; SymbolCreator: a0412235; VDC_V: 12; SwitchFunction: Off-Mom; PositionCount: 1; CurrentRating_mA: 50
LMT1 = LMT84LPM: 1.5V, TO-92, Analog Temperature Sensor with Class-AB Output, LP0003A; Manufacturer: Texas Instruments; SymbolCreator: a0411947; SizeArea_mm2: 18.4; SizeAreaWB_mm2: 39.76; SizeX_mm: 3.68; SizeY_mm: 5; SizeZ_mm: 9.33; CompType: IC; U/M: EA
LMT84_V+ MSP_V+ = M22-2510205: as J1 on sheet Board_IO_Interface
Logic_LED_Driver = SN74LVC1G27DBVR: Single 3-Input Positive-NOR Gate, DBV0006A; Manufacturer: Texas Instruments; SymbolCreator: Altium; SizeArea_mm2: 8.12; SizeAreaWB_mm2: 14.82; SizeX_mm: 2.8; SizeY_mm: 2.9; SizeZ_mm: 1.45; CompType: IC; U/M: EA
Low_Temp_LED1 = LTST-C170KFKT: LED, Orange, SMD; Manufacturer: Lite-On; Vf_V: 2; Value2: 2V; Io_A: 0.02; Value1: W; U/M: EA
MSP1 = MSP430FR2311IPW20R: Mixed-Signal Microcontroller, PW0020A; Manufacturer: Texas Instruments; SymbolCreator: Altium; SizeArea_mm2: 43.56; SizeAreaWB_mm2: 73.96; SizeX_mm: 6.6; SizeZ_mm: 1.2; CompType: IC; U/M: EA
Power = 150060BS75000: LED, Blue, SMD; Manufacturer: Wurth Elektronik; Vf_V: 3.2; Value2: 3.2V; Io_A: 0.03; Vr_V: 5; Tjmax_C: 85; Power_TotalModule: 0.105; Value1: 0.105W; Angle: 140; U/M: EA
R3-R5 R7 R8 = CRCW0402270RJNED: RES, 270, 5%, 0.063 W, 0402; Manufacturer: Vishay-Dale; CompType: Resistor; Value: 270; Value_Code: 270R; Tolerance_%: 5; Power_W: 0.063; Value2: 0.063W; VDC_V: 50; TempCo: 200 ppm/C; SizeArea_mm2: 0.5; SizeX_mm: 1; SizeZ_mm: 0.6; EIA_Code: E24; U/M: EA; AEC Category: Q200
R6 = CRCW04021K50FKED: RES, 1.50 k, 1%, 0.063 W, 0402; Manufacturer: Vishay-Dale; CompType: Resistor; Value: 1.50k; Res_ohm: 1500; Value_Code: 1k50; Tolerance_%: 1; Power_W: 0.063; Value2: 0.063W; VDC_V: 50; TempCo: 100 ppm/C; SizeArea_mm2: 0.5; SizeZ_mm: 0.6; EIA_Code: E96; U/M: EA; AEC Category: Q200
R9 = CRCW040247K0JNED: RES, 47 k, 5%, 0.063 W, 0402; Manufacturer: Vishay-Dale; CompType: Resistor; Value: 47k; Res_ohm: 47000; Value_Code: 47k0; Tolerance_%: 5; Power_W: 0.063; Value2: 0.063W; VDC_V: 50; TempCo: 200 ppm/C; SizeArea_mm2: 0.5; SizeX_mm: 1; SizeZ_mm: 0.6; EIA_Code: E24; U/M: EA; AEC Category: Q200
R24 R25 = RG2012P-473-B-T5: RES, 47.0 k, 0.1%, 0.125 W, 0805; Manufacturer: Susumu Co Ltd; CompType: Resistor; Value: 47.0k; Res_ohm: 47000; Value_Code: 47k0; Tolerance_%: 0.1; Power_W: 0.125; Value2: 0.125W; VDC_V: 100; TempCo: 25 ppm/C; SizeArea_mm2: 2.5; SizeX_mm: 2; SizeY_mm: 1.25; SizeZ_mm: 1.45; EIA_Code: E192; U/M: EA; AEC Category: Q200
System_Ok_LED1 = LTST-C170KGKT: LED, Green, SMD; Manufacturer: Lite-On; Vf_V: 2; Value2: 2V; Io_A: 0.02; Value1: W; U/M: EA

## Sheet Sensor_Filtering.SchDoc
size 431 x 279 mm; Date: Not shown in title block; ApprovedBy: Not shown in title block; CheckedBy: Not shown in title block; Author: Not shown in title block; CompanyName: Not shown in title block; Engineer: Not shown in title block; Organization: Not shown in title block; Address1: Not shown in title block; Address2: Not shown in title block; Address3: Not shown in title block; Address4: Not shown in title block; DocumentNumber: 1; Revision: Use project parameter SCH_Rev; SheetNumber: 4; SheetTotal: 5; PageSetup: Record=PageOptions¦CenterHorizontal=True¦CenterVertical=True¦PrintScale=1.00¦XCorrection=1.00¦YCorrection=1.00¦PrintKind=0¦BorderSize=5000000¦LeftOffset=0¦BottomOffset=0¦Orientation=2¦PaperLength=1000¦PaperWidth=1000¦Scale=100¦PaperSource=15¦PrintQuality=600¦MediaType=1¦DitherType=10¦PaperKind=Letter¦PrintScaleMode=1
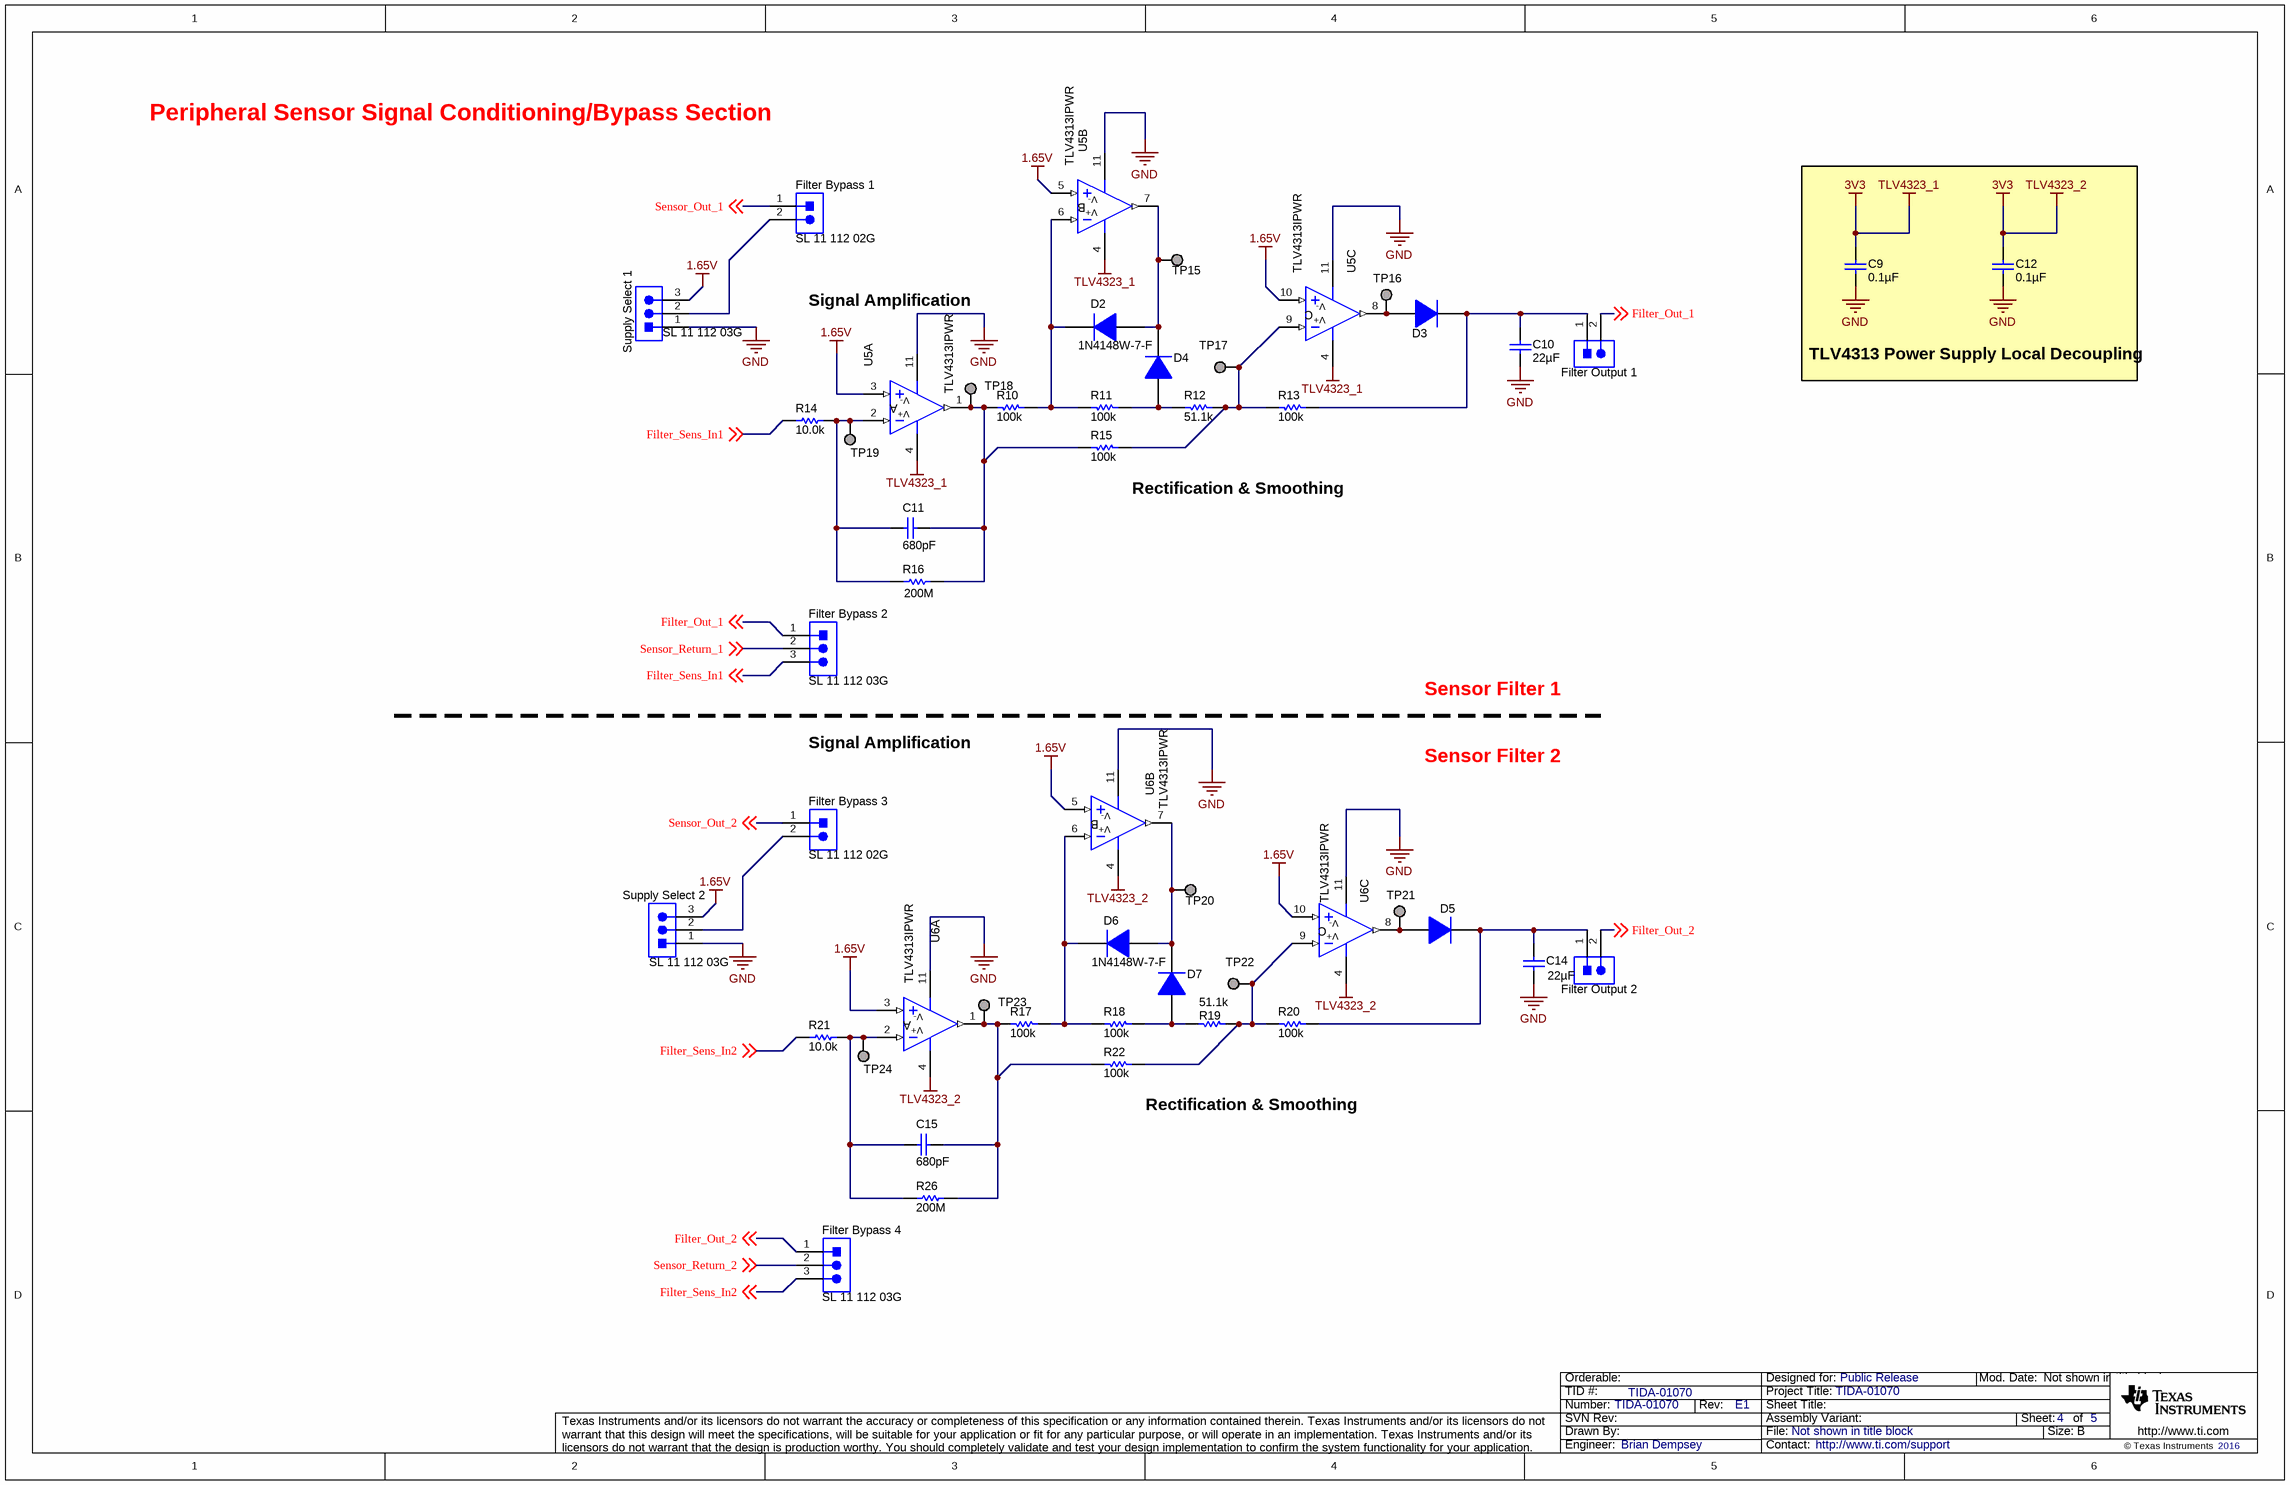
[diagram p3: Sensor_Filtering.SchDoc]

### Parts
C9  ValueDisplayed: 0.1µF  [0603]  (hidden comment: 0603YC104JAT2A)
C10  ValueDisplayed: 22µF  [1206_180]  (hidden comment: GRM31CR70J226KE19L)
C11  ValueDisplayed: 680pF  [0201]  (hidden comment: GRM033R71C681KA01D)
C12  ValueDisplayed: 0.1µF  [0603]  (hidden comment: 0603YC104JAT2A)
C14  ValueDisplayed: 22µF  [1206_180]  (hidden comment: GRM31CR70J226KE19L)
C15  ValueDisplayed: 680pF  [0201]  (hidden comment: GRM033R71C681KA01D)
D2  1N4148W-7-F  [SOD-123]
D3  1N4148W-7-F  [SOD-123]  (value not drawn)
D4  1N4148W-7-F  [SOD-123]  (value not drawn)
D5  1N4148W-7-F  [SOD-123]  (value not drawn)
D6  1N4148W-7-F  [SOD-123]
D7  1N4148W-7-F  [SOD-123]  (value not drawn)
Filter_Bypass_1  SL 11 112 02G  [Fischer_SL-11-112-02G]
Filter_Bypass_2  SL 11 112 03G  [Fischer_SL-11-112-03G]
Filter_Bypass_3  SL 11 112 02G  [Fischer_SL-11-112-02G]
Filter_Bypass_4  SL 11 112 03G  [Fischer_SL-11-112-03G]
Filter_Output_1  M22-2510205  [Harwin_M22-2510205]  (value not drawn)
Filter_Output_2  M22-2510205  [Harwin_M22-2510205]  (value not drawn)
R10  ValueDisplayed: 100k  [0402]  (hidden comment: RG1005P-104-B-T5)
R11  ValueDisplayed: 100k  [0402]  (hidden comment: RG1005P-104-B-T5)
R12  ValueDisplayed: 51.1k  [0402]  (hidden comment: CRCW040251K1FKED)
R13  ValueDisplayed: 100k  [0402]  (hidden comment: RG1005P-104-B-T5)
R14  ValueDisplayed: 10.0k  [0402]  (hidden comment: CRCW040210K0FKED)
R15  ValueDisplayed: 100k  [0402]  (hidden comment: RG1005P-104-B-T5)
R16  ValueDisplayed: 200M  [0603_HR]  (hidden comment: CRCW0603200MJPEAHR)
R17  ValueDisplayed: 100k  [0402]  (hidden comment: RG1005P-104-B-T5)
R18  ValueDisplayed: 100k  [0402]  (hidden comment: RG1005P-104-B-T5)
R19  ValueDisplayed: 51.1k  [0402]  (hidden comment: CRCW040251K1FKED)
R20  ValueDisplayed: 100k  [0402]  (hidden comment: RG1005P-104-B-T5)
R21  ValueDisplayed: 10.0k  [0402]  (hidden comment: CRCW040210K0FKED)
R22  ValueDisplayed: 100k  [0402]  (hidden comment: RG1005P-104-B-T5)
R26  ValueDisplayed: 200M  [0603_HR]  (hidden comment: CRCW0603200MJPEAHR)
Supply_Select_1  SL 11 112 03G  [Fischer_SL-11-112-03G]
Supply_Select_2  SL 11 112 03G  [Fischer_SL-11-112-03G]
TP15  TESTPOINT  [Keystone_5019]  (value not drawn)  (no BOM)
TP16  TESTPOINT  [Keystone_5019]  (value not drawn)  (no BOM)
TP17  TESTPOINT  [Keystone_5019]  (value not drawn)  (no BOM)
TP18  TESTPOINT  [Keystone_5019]  (value not drawn)  (no BOM)
TP19  TESTPOINT  [Keystone_5019]  (value not drawn)  (no BOM)
TP20  TESTPOINT  [Keystone_5019]  (value not drawn)  (no BOM)
TP21  TESTPOINT  [Keystone_5019]  (value not drawn)  (no BOM)
TP22  TESTPOINT  [Keystone_5019]  (value not drawn)  (no BOM)
TP23  TESTPOINT  [Keystone_5019]  (value not drawn)  (no BOM)
TP24  TESTPOINT  [Keystone_5019]  (value not drawn)  (no BOM)
U5  TLV4313IPWR  [PW0014A_N]  (parts A,B,C of 4)
U6  TLV4313IPWR  [PW0014A_N]  (parts A,B,C of 4)

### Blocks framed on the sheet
TLV4313 Power Supply Local Decoupling: C9 C12

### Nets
1.65V: Supply_Select_1.3 Supply_Select_2.3 U5.3(IN+) U5.5(IN+) U5.10(IN+) U6.3(IN+) U6.5(IN+) U6.10(IN+)
3V3: C9.2 C12.2 U5.4(V+) U6.4(V+)  [also labelled TLV4323_1, TLV4323_2]
GND: C9.1 C10.2 C12.1 C14.2 Supply_Select_1.1 Supply_Select_2.1 U5.11(V-) U6.11(V-)
Filter_Out_1: Filter_Bypass_2.1 Filter_Output_1.2 ; off-sheet Filter_Out_1
Filter_Out_2: Filter_Bypass_4.1 Filter_Output_2.2 ; off-sheet Filter_Out_2
Filter_Sens_In1: Filter_Bypass_2.3 R14.1 ; off-sheet Filter_Sens_In1
Filter_Sens_In2: Filter_Bypass_4.3 R21.2 ; off-sheet Filter_Sens_In2
Sensor_Out_1: Filter_Bypass_1.1 ; off-sheet Sensor_Out_1
Sensor_Out_2: Filter_Bypass_3.1 ; off-sheet Sensor_Out_2
Sensor_Return_1: Filter_Bypass_2.2 ; off-sheet Sensor_Return_1
Sensor_Return_2: Filter_Bypass_4.2 ; off-sheet Sensor_Return_2
NetC10_1: C10.1 D3.1(K) Filter_Output_1.1 R13.2
NetC11_1: C11.1 R10.1 R15.1 R16.2 TP18.1 U5.1(OUT)
NetC11_2: C11.2 R14.2 R16.1 TP19.1 U5.2(IN-)
NetC14_1: C14.1 D5.1(K) Filter_Output_2.1 R20.2
NetC15_1: C15.1 R17.1 R22.1 R26.2 TP23.1 U6.1(OUT)
NetC15_2: C15.2 R21.1 R26.1 TP24.1 U6.2(IN-)
NetD2_1: D2.1(K) R10.2 R11.1 U5.6(IN-)
NetD2_2: D2.2(A) D4.1(K) TP15.1 U5.7(OUT)
NetD3_2: D3.2(A) TP16.1 U5.8(OUT)
NetD4_2: D4.2(A) R11.2 R12.1
NetD5_2: D5.2(A) TP21.1 U6.8(OUT)
NetD6_1: D6.1(K) R17.2 R18.1 U6.6(IN-)
NetD6_2: D6.2(A) D7.1(K) TP20.1 U6.7(OUT)
NetD7_2: D7.2(A) R18.2 R19.1
NetFilter_Bypass_1_2: Filter_Bypass_1.2 Supply_Select_1.2
NetFilter_Bypass_3_2: Filter_Bypass_3.2 Supply_Select_2.2
NetR12_2: R12.2 R13.1 R15.2 TP17.1 U5.9(IN-)
NetR19_2: R19.2 R20.1 R22.2 TP22.1 U6.9(IN-)

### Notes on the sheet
- Peripheral Sensor Signal Conditioning/Bypass Section
- Signal Amplification
- (near R15) Rectification & Smoothing
- Sensor Filter 1
- Sensor Filter 2
- (near R22) Rectification & Smoothing

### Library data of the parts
C9 C12 = 0603YC104JAT2A: as C3 on sheet Board_IO_Interface
C10 C14 = GRM31CR70J226KE19L: CAP, CERM, 22 µF, 6.3 V, +/- 10%, X7R, 1206; Manufacturer: MuRata; Polarized: N; CompType: Capacitor; Value: 22uF; U/M: EA; Cap_F: 0.000022; Tolerance_%: 10; Value1: Unknown; VDC_V: 6.3; Value2: 6.3V; TaMin_C: -55; TaMax_C: 125; Cap_Case: 1206; SizeArea_mm2: 5.12; SizeAreaWB_mm2: 10.92; SizeX_mm: 3.2; SizeY_mm: 1.6; SizeZ_mm: 1.8; AEC Category: Q200
C11 C15 = GRM033R71C681KA01D: CAP, CERM, 680 pF, 16 V, +/- 10%, X7R, 0201; Manufacturer: MuRata; Polarized: N; CompType: Capacitor; Value: 680pF; U/M: EA; Cap_F: 0.00000000068; Tolerance_%: 10; Value1: Unknown; VDC_V: 16; Value2: 16V; TaMin_C: -55; TaMax_C: 125; SizeArea_mm2: 0.18; SizeAreaWB_mm2: 2.08; SizeX_mm: 0.6; SizeY_mm: 0.3; SizeZ_mm: 0.26; AEC Category: Q200
D2-D7 = 1N4148W-7-F: Diode, Ultrafast, 100 V, 0.15 A, SOD-123; Manufacturer: Diodes Inc.; U/M: EA; Vf_V: 1.25; Value: 100V; Value1: 0.15A; Value2: 1.25V; Io_A: 0.15; Vr_V: 100; TJmax_C: 150; SizeAreaWB_mm2: 13.095; SizeArea_mm2: 6.545; SizeX_mm: 3.85; SizeY_mm: 1.7; SizeZ_mm: 1.35; AEC Category: Q101
Filter_Bypass_1 Filter_Bypass_3 = SL 11 112 02G: Header, 2.54mm, 2x1, Gold, TH; Manufacturer: Fischer Elektronik; SymbolCreator: a0412235
Filter_Bypass_2 Filter_Bypass_4 Supply_Select_1 Supply_Select_2 = SL 11 112 03G: as Ref._VSEL1 on sheet Board_IO_Interface
Filter_Output_1 Filter_Output_2 = M22-2510205: as J1 on sheet Board_IO_Interface
R10 R11 R13 R15 R17 R18 R20 R22 = RG1005P-104-B-T5: RES, 100 k, 0.1%, 0.063 W, 0402; Manufacturer: Susumu Co Ltd; CompType: Resistor; Value: 100k; Res_ohm: 100000; Tolerance_%: 0.1; Power_W: 0.063; Value2: 0.063W; TempCo: 25 ppm/C; SizeArea_mm2: 0.5; SizeX_mm: 1; SizeZ_mm: 0.6; EIA_Code: E192; U/M: EA; AEC Category: Q200
R12 R19 = CRCW040251K1FKED: RES, 51.1 k, 1%, 0.063 W, 0402; Manufacturer: Vishay-Dale; CompType: Resistor; Value: 51.1k; Res_ohm: 51100; Value_Code: 51k1; Tolerance_%: 1; Power_W: 0.063; Value2: 0.063W; VDC_V: 50; TempCo: 100 ppm/C; SizeArea_mm2: 0.5; SizeZ_mm: 0.6; EIA_Code: E96; U/M: EA; AEC Category: Q200
R14 R21 = CRCW040210K0FKED: as R30 on sheet Ac to DC Converter
R16 R26 = CRCW0603200MJPEAHR: RES, 200M, 5%, 0.1 W, 0603; Manufacturer: Vishay-Dale; CompType: Resistor; Value: 200Meg; Res_ohm: 200000000; Tolerance_%: 5; Power_W: 0.1; Value2: 0.1W; VDC_V: 75; TempCo: 500 ppm/C; SizeArea_mm2: 1.3175; SizeX_mm: 1.55; SizeY_mm: 0.85; SizeZ_mm: 0.5; U/M: EA; AEC Category: Q200; AEC Qualified: N
TP15-TP24 = 5019: as TP1 on sheet Ac to DC Converter
U5 U6 = TLV4313IPWR: Low-Power, Rail-to-Rail In/Out, 500-uV Typical Offset, 1-MHz Operational Amplifier for Cost-Sensitive System, PW0014A; Manufacturer: Texas Instruments; SymbolCreator: a0412235; SizeArea_mm2: 32; SizeAreaWB_mm2: 58.8; SizeX_mm: 6.4; SizeY_mm: 5; SizeZ_mm: 1.2; CompType: IC; U/M: EA

## Sheet TIDA-01070__EVM_Hardware.SchDoc
size 431 x 279 mm; Date: Not shown in title block; ApprovedBy: Not shown in title block; CheckedBy: Not shown in title block; Author: Not shown in title block; CompanyName: Not shown in title block; Engineer: Not shown in title block; Organization: Not shown in title block; Address1: Not shown in title block; Address2: Not shown in title block; Address3: Not shown in title block; Address4: Not shown in title block; DocumentNumber: 1; Revision: Use project parameter SCH_Rev; SheetNumber: 5; SheetTotal: 5; PageSetup: Record=PageOptions¦CenterHorizontal=True¦CenterVertical=True¦PrintScale=1.00¦XCorrection=1.00¦YCorrection=1.00¦PrintKind=0¦BorderSize=5000000¦LeftOffset=0¦BottomOffset=0¦Orientation=2¦PaperLength=1000¦PaperWidth=1000¦Scale=100¦PaperSource=15¦PrintQuality=600¦MediaType=1¦DitherType=10¦PaperKind=Letter¦PrintScaleMode=1
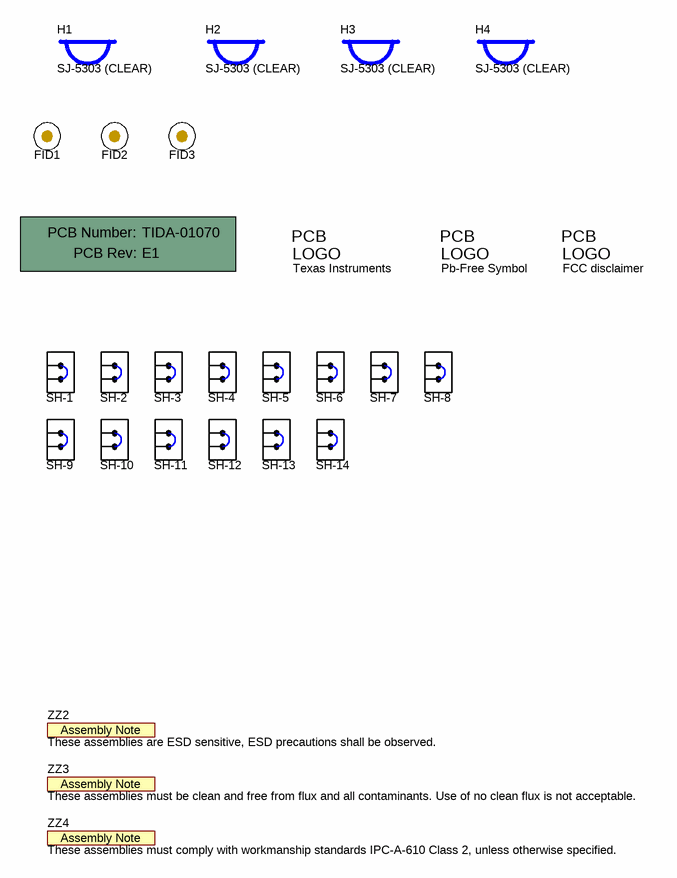
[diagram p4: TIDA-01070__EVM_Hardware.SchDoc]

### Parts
!PCB  Printed Circuit Board  (value not drawn)  (mechanical)
FID1  Fiducial  [Fiducial10-20]  (value not drawn)
FID2  Fiducial  [Fiducial10-20]  (value not drawn)
FID3  Fiducial  [Fiducial10-20]  (value not drawn)
H1  SJ-5303 (CLEAR)  [Bumpon_SJ5003Transparent]
H2  SJ-5303 (CLEAR)  [Bumpon_SJ5003Transparent]
H3  SJ-5303 (CLEAR)  [Bumpon_SJ5003Transparent]
H4  SJ-5303 (CLEAR)  [Bumpon_SJ5003Transparent]
Logo1  Texas Instruments  [TI_Stacked_Overlay_Small]  (no BOM)
Logo2  Pb-Free Symbol  [Pb-Free_Overlay_Small]  (no BOM)
Logo3  FCC disclaimer  [FCC_disclaimer]  (no BOM)
SH-1  969102-0000-DA  [SNT-100-BK-G]  (value not drawn)
SH-2  969102-0000-DA  [SNT-100-BK-G]  (value not drawn)
SH-3  969102-0000-DA  [SNT-100-BK-G]  (value not drawn)
SH-4  969102-0000-DA  [SNT-100-BK-G]  (value not drawn)
SH-5  969102-0000-DA  [SNT-100-BK-G]  (value not drawn)
SH-6  969102-0000-DA  [SNT-100-BK-G]  (value not drawn)
SH-7  969102-0000-DA  [SNT-100-BK-G]  (value not drawn)
SH-8  969102-0000-DA  [SNT-100-BK-G]  (value not drawn)
SH-9  2SN-BK-G  [2SN-BK-G]  (value not drawn)
SH-10  2SN-BK-G  [2SN-BK-G]  (value not drawn)
SH-11  2SN-BK-G  [2SN-BK-G]  (value not drawn)
SH-12  2SN-BK-G  [2SN-BK-G]  (value not drawn)
SH-13  2SN-BK-G  [2SN-BK-G]  (value not drawn)
SH-14  2SN-BK-G  [2SN-BK-G]  (value not drawn)
ZZ2  These assemblies are ESD sensitive, ESD precautions shall be observed.  [AssemblyNote]  (no BOM)
ZZ3  These assemblies must be clean and free from flux and all contaminants. Use of no clean flux is not acceptable.  [AssemblyNote]  (no BOM)
ZZ4  These assemblies must comply with workmanship standards IPC-A-610 Class 2, unless otherwise specified.  [AssemblyNote]  (no BOM)

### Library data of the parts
!PCB = PCB: Manufacturer: Any; PartNumber: TIDA-01070; SymbolCreator: a0412235
FID1-FID3 = Fiducial: Fiducial mark.  There is nothing to buy or mount.; SymbolCreator: codlsc
H1-H4 = SJ-5303 (CLEAR): Bumpon, Hemisphere, 0.44 X 0.20, Clear; Manufacturer: 3M; SymbolCreator: a0412235
Logo1 = TI_Logo: Texas Instrument Corporate Signature; SymbolCreator: codlsc
Logo2 = Pb-Free: SymbolCreator: a0412235
Logo3 = FCC_disclaimer: SymbolCreator: codlsc
SH-1-SH-8 = 969102-0000-DA: Shunt, 100mil, Gold plated, Black; Manufacturer: 3M; Alternate Manufacturer: Samtec; Value: 1x2; Note: You can "mate" this to a header by matching the designator.  i.e. use SH-J3 for header J3
SH-9-SH-14 = 2SN-BK-G: Shunt, 2mm, Gold plated, Black; Manufacturer: Samtec; Value: 1x2; Note: You can "mate" this to a header by matching the designator.  i.e. use SH-J3 for header J3
ZZ2-ZZ4 = AssemblyNote: SymbolCreator: codlsc

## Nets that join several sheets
1.65V: Board_IO_Interface (5 pins), Sensor_Filtering (8 pins)
3V3: Board_IO_Interface (7 pins), Internal_Processing (11 pins), Sensor_Filtering (C9.2 C12.2 U5.4 U6.4)
GND: Ac to DC Converter (14 pins), Board_IO_Interface (16 pins), Internal_Processing (20 pins), Sensor_Filtering (8 pins)
5VDC_P: Ac to DC Converter (C16.1 L1.2 R28.2), Board_IO_Interface (J1.1 Main_V+_Test.1 Power_Jumper1.1)
DIO8_MISO: Board_IO_Interface (I/O_Block1.6 J2.13), Internal_Processing (MSP1.8)
DIO9_MOSI: Board_IO_Interface (I/O_Block1.7 J2.11), Internal_Processing (MSP1.7)
DIO13_BTN1: Board_IO_Interface (I/O_Block1.5 J2.15), Internal_Processing (MSP1.9)
DIO23_Analog: Board_IO_Interface (I/O_Block1.1 J3.4), Internal_Processing (Dirty_Filter_LED1.1 Logic_LED_Driver.6 MSP1.10)
DIO24_Analog: Board_IO_Interface (I/O_Block1.2 J3.12), Internal_Processing (Dirty_Coil_LED1.1 Logic_LED_Driver.3 MSP1.11)
DIO25_Analog: Board_IO_Interface (I/O_Block1.4 J3.5), Internal_Processing (MSP1.12)
DIO26_Analog: Board_IO_Interface (I/O_Block1.3 J3.7), Internal_Processing (Logic_LED_Driver.1 Low_Temp_LED1.1 MSP1.13)
Filter_Out_1: Internal_Processing (Filter_Out_1.1 MSP1.19), Sensor_Filtering (Filter_Bypass_2.1 Filter_Output_1.2)
Filter_Out_2: Internal_Processing (Filter_Out_2.1 MSP1.18), Sensor_Filtering (Filter_Bypass_4.1 Filter_Output_2.2)
nRST: Board_IO_Interface (JTAG1.1 U4.1), Internal_Processing (5 pins)
Reference_Selector: Board_IO_Interface (Ref._VSEL1.2), Internal_Processing (MSP1.2 Reference.1)
Sensor_Out_1: Board_IO_Interface (External_Sensor_Terminal1.2), Sensor_Filtering (Filter_Bypass_1.1)
Sensor_Out_2: Board_IO_Interface (External_Sensor_Terminal2.2), Sensor_Filtering (Filter_Bypass_3.1)
Sensor_Return_1: Board_IO_Interface (External_Sensor_Terminal1.1), Sensor_Filtering (Filter_Bypass_2.2)
Sensor_Return_2: Board_IO_Interface (External_Sensor_Terminal2.1), Sensor_Filtering (Filter_Bypass_4.2)
System_On: Board_IO_Interface (I/O_Block1.8), Internal_Processing (MSP1.17 R25.2)
TEST: Board_IO_Interface (JTAG1.7 U3.1), Internal_Processing (MSP1.3)
UART_RX: Board_IO_Interface (U1.1 UART_RX_Jumper1.2), Internal_Processing (MSP1.16)
UART_TX: Board_IO_Interface (U2.1 UART_TX_Jumper1.2), Internal_Processing (MSP1.15)

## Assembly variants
001: not fitted FID1 FID2 FID3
